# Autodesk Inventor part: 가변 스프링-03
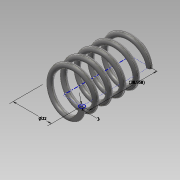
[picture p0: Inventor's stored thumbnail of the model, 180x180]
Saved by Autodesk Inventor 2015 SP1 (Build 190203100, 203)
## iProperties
Created: 2014-12
Part Number: 가변 스프링-03
Material: 강철, 탄소
Document SubType Name: Modeling
Designer: mypark
Density: 7.85 g/cm^3
Appearance: 반연마
Mass: 18.8653 g
Surface Area: 32.569 cm^2
Volume: 2.40323 cm^3
Author: mypark
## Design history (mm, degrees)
sketch "스케치1"
  geometry: L1 (0, 0)-(11, 0); L2 (11, 0)-(11, 38.958); L3 (11, 38.958)-(0, 38.958); L4 (0, 38.958)-(0, 0); C1 r 1.5 at (11, 0)
  constraints: 8 end point, 2 parallel, 1 centre point, 1 coincident, 1 horizontal, 1 perpendicular
  dimensions: "d0" = 38.95829 distance of L1.end L2.end (derived); "d1" = 3 diameter of C1; "d2" = 22 diameter of C1.centre L4
feature "코일1" sketch "스케치1" pitch "d3" = 10; turns "d5" = 5; dims "d4" = 38.95829 (= d0), "d6" = 0, angle "d7" = 90 deg, angle "d8" = 90 deg, "d9" = 0, "d10" = 0
sketch "스케치2"
  geometry: L1 (-12.5, 0)-(-9.5, 0) reference; 1 further point
  constraints: 1 horizontal alignment
extrude "돌출1" cut sketch "스케치2" stored distance "d11" = 10; taper "d12" = 0 deg
node "작업 평면1"
sketch "스케치3"
  geometry: L1 (3, 0)-(0, 0) reference; 1 further point
  constraints: 1 horizontal alignment
extrude "돌출2" cut sketch "스케치3" stored distance "d13" = 10; taper "d14" = 0 deg
node "솔리드1"
node "절단 모서리 투영1"
node "절단 모서리 투영2"
